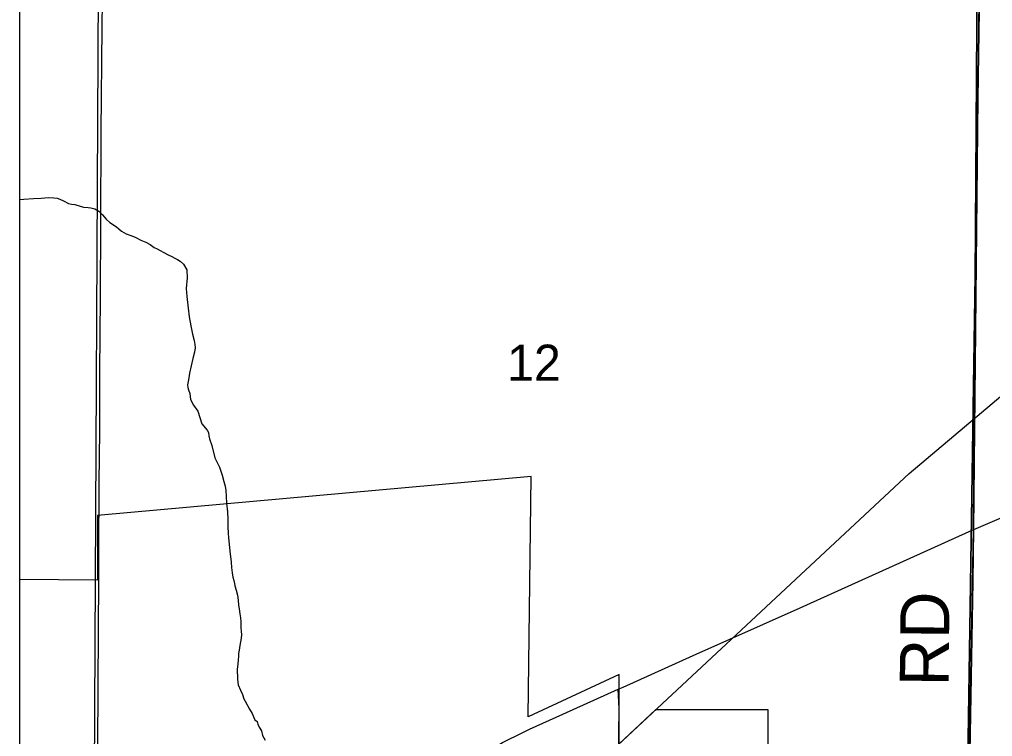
# Model space of a CAD drawing. Extents: x 0 to 34, y 0 to 22.
# Drawn here: x 2.1 to 3.229, y 18.295 to 19.126 of the extents above; entities that cross this region are included whole.
import ezdxf

# ---------------------------------------------------------------- set-up
doc = ezdxf.new("R2010")
doc.units = 0
for name, color, linetype in [('Default', 7, 'Continuous'), ('GM_X_City_Street', 7, 'Continuous'), ('GM_X_Minor_River', 7, 'Continuous'), ('GM_X_Rail_Line', 7, 'Continuous'), ('GM_X_Section', 7, 'Continuous'), ('GM_X_Section_Text', 7, 'Continuous'), ('GM_X_State_Route', 7, 'Continuous'), ('GM_X_Township_Road', 7, 'Continuous'), ('GM_X_Township_Road_Text', 7, 'Continuous'), ('SH_Cut_Line', 7, 'Continuous'), ('SH_Data', 7, 'Continuous')]:
    doc.layers.add(name, color=color, linetype=linetype)

msp = doc.modelspace()

# ---------------------------------------------------------------- linework, layer by layer
at = {"layer": 'Default'}
msp.add_lwpolyline([(2.1, 19.2367), (2.1, 18.2496), (2.187, 18.2488), (2.1921, 19.2365)], close=True, dxfattribs=at)
msp.add_lwpolyline([(3.4447, 17.732), (3.1921, 17.7348), (3.1889, 17.5591), (2.9487, 17.6473), (2.9487, 17.7603), (2.881, 17.7674), (2.881, 17.9186), (2.9686, 17.9186), (2.9685, 18.3256), (2.8381, 18.3256), (2.7959, 18.2862), (2.7959, 18.3665), (2.6903, 18.3173), (2.6935, 18.5959), (2.1906, 18.5508), (2.1906, 18.476), (2.1, 18.4765), (2.1, 16.2268)], dxfattribs=at)
at = {"layer": 'GM_X_City_Street'}
msp.add_lwpolyline([(2.7826, 17.7187), (2.7853, 17.7263), (2.7866, 17.736), (2.7876, 17.7736), (2.7892, 17.8722), (2.791, 17.9966), (2.7929, 18.1171), (2.7948, 18.2377), (2.7957, 18.3272), (2.7948, 18.3493)], dxfattribs=at)
at = {"layer": 'GM_X_Minor_River'}
for points in [[(2.1, 18.9173), (2.1052, 18.9175), (2.1162, 18.9183), (2.1253, 18.9188), (2.1336, 18.9196), (2.1397, 18.9192), (2.1439, 18.9189), (2.1469, 18.9177), (2.1511, 18.9155), (2.1568, 18.9125), (2.1602, 18.9117), (2.1644, 18.9114), (2.1705, 18.9095), (2.1743, 18.9084), (2.1796, 18.908), (2.1827, 18.9076), (2.1876, 18.9062), (2.1922, 18.9035), (2.1964, 18.8994), (2.2006, 18.8944), (2.2048, 18.8907), (2.2124, 18.8854), (2.2151, 18.8831), (2.2185, 18.8805), (2.2238, 18.8775), (2.2303, 18.8752), (2.2352, 18.873), (2.2409, 18.8699), (2.2466, 18.8677), (2.2516, 18.8651), (2.2562, 18.8617), (2.2596, 18.8598), (2.2634, 18.8579), (2.2676, 18.8556), (2.2725, 18.853), (2.2767, 18.8511), (2.2801, 18.8492), (2.2832, 18.8477), (2.2866, 18.8455), (2.2904, 18.8421), (2.2942, 18.8356), (2.2947, 18.8265), (2.2936, 18.814), (2.294, 18.8049), (2.2956, 18.7912), (2.2968, 18.781), (2.2987, 18.7707), (2.3007, 18.7612), (2.3026, 18.7536), (2.3034, 18.7491), (2.3038, 18.7453), (2.3031, 18.74), (2.3012, 18.7327), (2.2971, 18.716), (2.2964, 18.7103), (2.2956, 18.7061), (2.2949, 18.7023), (2.2953, 18.6993), (2.2961, 18.6966), (2.2976, 18.6921), (2.2984, 18.6852), (2.3019, 18.6788), (2.3068, 18.6716), (2.3115, 18.6572), (2.3179, 18.6496), (2.3195, 18.647), (2.3199, 18.6432), (2.3203, 18.6398), (2.3233, 18.6318), (2.3265, 18.6178), (2.3322, 18.6068), (2.3353, 18.5977), (2.3372, 18.5901), (2.3388, 18.5848), (2.3395, 18.5798), (2.34, 18.573), (2.3404, 18.565), (2.3412, 18.5552), (2.3416, 18.5461), (2.3417, 18.5381), (2.3421, 18.5301), (2.3425, 18.5252), (2.3433, 18.5172), (2.3445, 18.5058), (2.3453, 18.5001), (2.3457, 18.4967), (2.3461, 18.4906), (2.3469, 18.4842), (2.3476, 18.4792), (2.3488, 18.4754), (2.3496, 18.472), (2.35, 18.4694), (2.3515, 18.4641), (2.3531, 18.4584), (2.3538, 18.4527), (2.3542, 18.447), (2.355, 18.4424), (2.3558, 18.4367), (2.3566, 18.4322)], [(2.3566, 18.4322), (2.357, 18.4276), (2.357, 18.4208), (2.3574, 18.4162), (2.3575, 18.4128), (2.3571, 18.4086), (2.3564, 18.4045), (2.3556, 18.3999), (2.3549, 18.3946), (2.3541, 18.3908), (2.3542, 18.3877), (2.3538, 18.3832), (2.3534, 18.379), (2.3531, 18.3752), (2.3527, 18.3725), (2.3528, 18.3615), (2.3532, 18.357), (2.3536, 18.3543), (2.3563, 18.3482), (2.3589, 18.3433), (2.3605, 18.3384), (2.362, 18.3354), (2.367, 18.3263), (2.3701, 18.3213), (2.3731, 18.3138), (2.3758, 18.3119), (2.3766, 18.3088), (2.3781, 18.3054), (2.3808, 18.3013), (2.3819, 18.2956), (2.385, 18.2903)]]:
    msp.add_lwpolyline(points, dxfattribs=at)
at = {"layer": 'GM_X_Rail_Line'}
msp.add_lwpolyline([(2.3438, 17.8832), (2.4082, 17.9379), (2.5423, 18.061), (2.7943, 18.2844), (3.1322, 18.5996), (3.3125, 18.7514), (3.4225, 18.8451), (3.8301, 19.2157), (4.2487, 19.5941), (4.47, 19.794), (4.5566, 19.8598), (4.6465, 19.9302), (4.7011, 19.9679), (5.2057, 20.3431), (5.7213, 20.7403), (5.9437, 20.9)], dxfattribs=at)
at = {"layer": 'GM_X_Section'}
for points in [[(2.1921, 19.2365), (3.2151, 19.2391), (3.2, 18.2405), (2.187, 18.2488)], [(3.2151, 19.2391), (4.2026, 19.2018), (4.1997, 18.1993), (3.2, 18.2405)]]:
    msp.add_lwpolyline(points, close=True, dxfattribs=at)
at = {"layer": 'GM_X_State_Route'}
for points in [[(3.2071, 18.5344), (3.2912, 18.5707), (3.438, 18.6337), (3.6313, 18.7164), (3.7384, 18.7627), (3.8083, 18.7947), (3.868, 18.8264), (3.9451, 18.8676), (4.0083, 18.9108), (4.0708, 18.9549), (4.1126, 18.9832), (4.1555, 19.0093), (4.202, 19.0361), (4.323, 19.1042), (4.4211, 19.1597), (4.4727, 19.1914), (4.604, 19.2798), (4.6509, 19.3078)], [(2.1923, 18.5601), (2.1924, 18.5889), (2.1931, 18.6485), (2.1933, 18.717), (2.1939, 18.804), (2.1946, 18.8907), (2.1948, 18.9957), (2.196, 19.1169), (2.1975, 19.241)], [(2.1921, 18.4896), (2.1922, 18.5363), (2.1923, 18.5601)], [(2.8003, 18.3517), (2.8815, 18.3883), (3.0057, 18.4438), (3.1454, 18.5067), (3.2019, 18.5321), (3.2071, 18.5344)], [(2.1907, 18.2395), (2.1909, 18.2796), (2.1915, 18.355), (2.1918, 18.4146), (2.1921, 18.4794), (2.1921, 18.4896)], [(2.6919, 18.303), (2.7303, 18.3206), (2.7948, 18.3493), (2.8003, 18.3517)], [(2.3675, 17.8737), (2.3772, 17.8874), (2.4011, 17.9255), (2.4193, 17.9549), (2.4377, 17.9837), (2.4622, 18.0233), (2.4822, 18.0546), (2.5203, 18.1147), (2.5525, 18.1647), (2.5743, 18.199), (2.5949, 18.2292), (2.6056, 18.2439), (2.6203, 18.2587), (2.6389, 18.2738), (2.6603, 18.2875), (2.6848, 18.2997), (2.6919, 18.303)]]:
    msp.add_lwpolyline(points, dxfattribs=at)
at = {"layer": 'GM_X_Township_Road'}
msp.add_line((3.2071, 18.5344), (3.2146, 19.245), dxfattribs=at)
for points in [[(3.1491, 14.2171), (3.1576, 14.794), (3.1628, 15.2158), (3.1774, 16.6199), (3.1774, 16.6219), (3.1894, 17.563), (3.1895, 17.5705), (3.1896, 17.5787), (3.2069, 18.535), (3.2116, 19.2346), (3.2118, 19.2455), (3.2241, 20.2443), (2.209, 20.2314), (2.1, 20.2296), (2.1, 14.2219)], [(8.9, 14.1483), (8.9, 20.2053), (7.2271, 20.2132), (6.4763, 20.2191), (6.0936, 20.222), (5.2207, 20.2288), (4.224, 20.2365), (3.2241, 20.2443), (3.2118, 19.2455), (3.2116, 19.2346), (3.2069, 18.535), (3.1896, 17.5787), (3.1895, 17.5705), (3.1894, 17.563), (3.1774, 16.6219), (3.1774, 16.6199), (3.1628, 15.2158), (3.1576, 14.794), (3.1491, 14.2171)], [(3.1968, 17.7272), (3.1972, 17.7655), (3.2017, 18.1538), (3.2027, 18.2535), (3.2066, 18.4741), (3.2071, 18.5344)]]:
    msp.add_lwpolyline(points, dxfattribs=at)
at = {"layer": 'SH_Cut_Line'}
msp.add_lwpolyline([(8.9, 14.1483), (8.9, 20.9), (2.1, 20.9), (2.1, 14.2219)], dxfattribs=at)
at = {"layer": 'SH_Data'}
msp.add_line((2.1, 20.9), (2.1, 14.1), dxfattribs=at)

# ---------------------------------------------------------------- texts
at = {"layer": 'GM_X_Section_Text'}
msp.add_text('12', height=0.04186, rotation=0, dxfattribs=at).set_placement((2.6658, 18.707))
at = {"layer": 'GM_X_Township_Road_Text'}
msp.add_text('RD', height=0.05682, rotation=89.5063, dxfattribs=at).set_placement((3.1781, 18.3526))

doc.saveas('drawing.dxf')
